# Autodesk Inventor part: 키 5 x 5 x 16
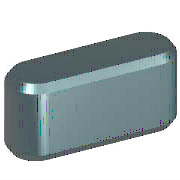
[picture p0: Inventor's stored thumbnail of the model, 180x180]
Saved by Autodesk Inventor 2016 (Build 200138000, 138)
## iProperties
IsCustomPart: 1
Created: 2012-02
Part Number: 키 5 x 5 x 16
Material: 강철, 연강
Description: 키 및 해당 키홈
Document SubType Name: Modeling
Standard: KS B 1311
Designer: mduedu
Standards Organization: KS
Language: ko-KR
Size Designation: 5 x 5 x 16
Categories: <MemberInstance><Categories><Category DisplayName="샤프트 부품" InternalName="7f7aeb1f-a693-4053-b835-cee3144e0d98" Mnemonic="SHFT"><Category DisplayName="키" Interna
Density: 1 g/cm^3
Appearance: 노란색
Author: mduedu
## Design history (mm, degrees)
workplane "Work Plane1"
workplane "Work Plane2"
sketch "스케치1"
  geometry: L1 (2.5, 2.5)-(11.5, 2.5); L2 (11.5, -2.5)-(2.5, -2.5); L3 (0, 8.9)-(0, -4.4) reference; L4 (-3.2, 0)-(19.2, 0) reference; L5 (14, 0)-(14, 7); A1 r 2.5 centre (2.5, 0) between (2.5, 2.5) and (2.5, -2.5); A2 r 2.5 centre (11.5, 0) between (11.5, -2.5) and (11.5, 2.5)
  constraints: 6 end point, 5 point on circle, 4 tangent, 3 point on line, 2 centre point, 1 horizontal, 1 parallel, 1 perpendicular
  dimensions: "d0" = 2.5 radius of A1 (= 0.5 x PB); "d13" = 2.5 radius of A2 (= 0.5 x PB); "d14" = 14 distance between parallel lines of L5 L3 (= NLG)
extrude "본체1" new body sketch "스케치1" taper "d3" = 0 deg; stored distance "d4" = 10
workplane "Work Plane3"
body "Solid1"
chamfer "모따기1" distance "d8" = 0.4 (= PHH); stored, may be unused: second distance "d9" = 0.4 (= PHH), angle "d15" = 45 deg
other parameters: "d1" = -3 (= -PNT), "d2" = 2 (= PH - PNT), "NLG" = 14 [user parameter; used in 3 equation terms], "PB" = 5 [user parameter; used in 2 equation terms], "PNT" = 3 [user parameter; used in 2 equation terms], "PH" = 5 [user parameter; used in 1 equation term], "PHH" = 0.4 [user parameter; used in 2 equation terms], "d10" = 0, "d16" = 0, "d17" = 0, "d18" = 0, "WDMIN" = 12 [user parameter], "PLB2" = 14 (= NLG) [user parameter], "WDMAX" = 17 [user parameter], "PLB1" = 14 (= NLG) [user parameter], "RR" = 0.16 [user parameter], "PUEB" = 2.3 [user parameter]
